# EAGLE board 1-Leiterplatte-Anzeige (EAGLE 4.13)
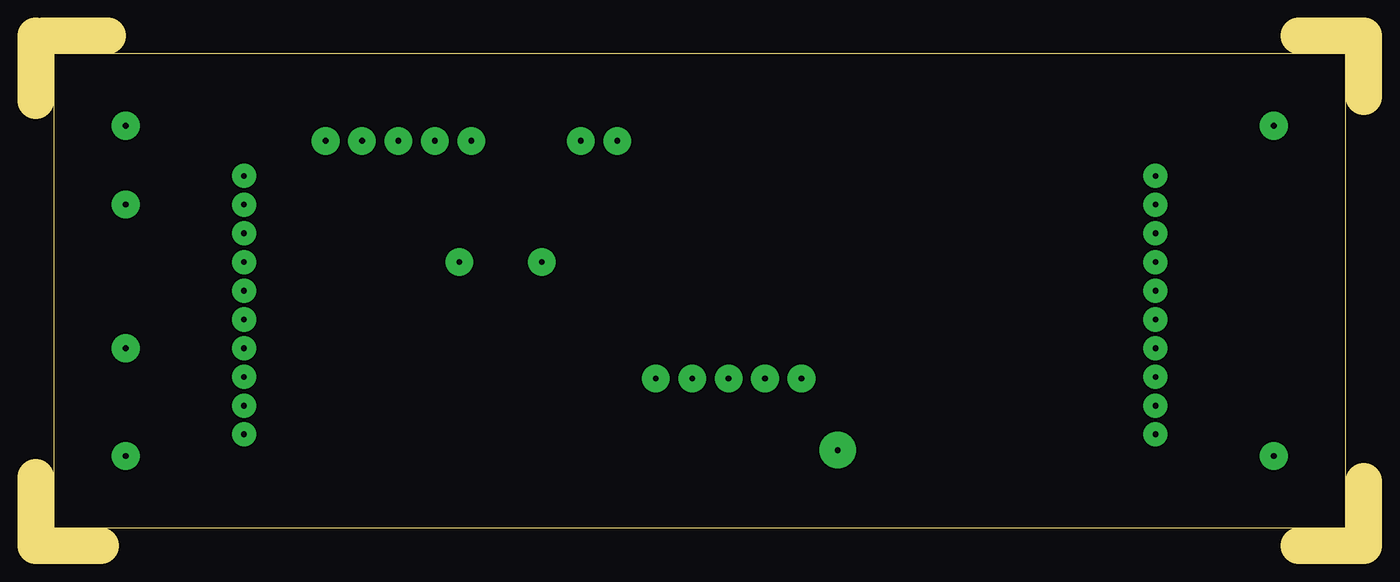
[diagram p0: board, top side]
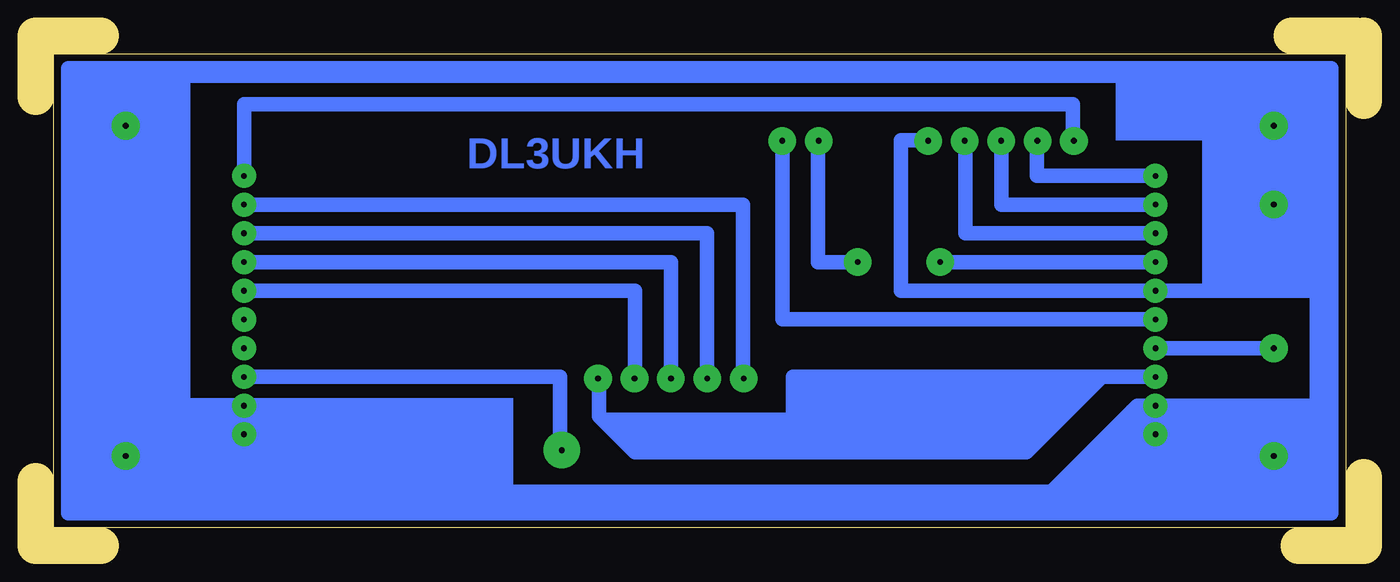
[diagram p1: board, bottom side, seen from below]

Size 92.5 x 35.5 mm. Coordinates in mm from the lower left corner, seen from the top.
Outline: 0.5,35.5 5,35.5
Outline: 0,31 0,35.5
Outline: 0,0.25 0,4.75
Outline: 4.5,0 0,0
Outline: 88,35.5 92.5,35.5 92.5,31.25
Outline: 92.5,4.5 92.5,0 88,0
Outline: 1.25,1.25 91.25,1.25 91.25,34.25 1.25,34.25 1.25,1.25
Copper layers (1*16): Top 0.035mm / dielectric 1.5mm / Bottom 0.035mm
Design rules "default": minimum track width 10mil, minimum drill 24mil, track to track 8mil, track to pad 8mil, pad to pad 8mil, via to via 8mil, smd to smd 8mil, copper to edge 40mil, drill to drill 8mil, minimum pad ring 10mil, minimum via ring 8mil, stop-mask expansion 4mil, vias tented up to drill 0mil, thermal gap 10mil

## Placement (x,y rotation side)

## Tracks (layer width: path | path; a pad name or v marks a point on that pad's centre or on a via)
S$1  (via drill 0.4 pad 1.93)
  other vias: 6.25,6.25
S$2  (via drill 0.4 pad 1.93)
  other vias: 6.25,29.25
S$3  (via drill 0.4 pad 1.93)
  other vias: 86.25,6.25
S$4  (via drill 0.4 pad 1.93)
  other vias: 86.25,29.25
S$5
  Bottom 1.016: 82.25,2.5 82.25,33.25 87,33.25 | 10,33.25 10.25,33.25 | 10,33.25 87,33.25 | 87,33.25 90.25,33.25 90.25,2.25 2.25,2.25 2.25,33.25 10,33.25
S$6  (via drill 0.4 pad 1.68, 0.4 pad 1.93)
  Bottom 1.016: 43.25,11.75 43.25,23.75 v78,23.75
  other vias: 43.18,11.65
S$7  (via drill 0.4 pad 1.68, 0.4 pad 1.93)
  Bottom 1.016: 6,13.75 v14.5,13.75 | 2.5,17.75 3.25,17.75 | 3.25,17.75 v14.5,17.75 32.25,17.75 32.25,28.25 30.25,28.25 | 20.75,3.75 16.75,7.75 v14.5,7.75 | 22,3.5 15.75,9.75 v14.5,9.75 | v14.5,7.75 9.5,7.75 | v14.5,9.75 v14.5,7.75 | 10.25,9.75 v14.5,9.75 | 10.25,9.75 3.25,9.75 | 3.25,9.75 2.75,9.75 | 10.25,2.5 10.25,9.75 | 3.25,17.75 3.25,9.75
  other vias: 30.34,28.19
S$8  (via drill 0.4 pad 1.68)
  Bottom 1.016: v14.5,15.75 22.75,15.75
S$10  (via drill 0.4 pad 1.68, 0.4 pad 1.93)
  Bottom 1.016: v14.5,19.75 v29.5,19.75
S$11  (via drill 0.4 pad 1.93)
  other vias: 6.25,13.75
S$12  (via drill 0.4 pad 1.93)
  other vias: 6.25,23.75
S$14  (via drill 0.4 pad 1.68)
  Bottom 1.016: v78,9.75 82.5,9.75
S$15  (via drill 0.4 pad 1.68, 0.4 pad 1.93)
  Bottom 1.016: 45.75,11.75 45.75,21.75 v78,21.75
  other vias: 45.72,11.65
S$16  (via drill 0.4 pad 1.68)
  other vias: 78,13.75
S$17  (via drill 0.4 pad 1.68)
  other vias: 78,15.75
S$18  (via drill 0.4 pad 1.68, 0.4 pad 1.93)
  Bottom 1.016: 48.25,11.75 48.25,19.75 v78,19.75
  other vias: 48.26,11.65
S$19  (via drill 0.4 pad 1.68, 0.4 pad 1.93)
  Bottom 1.016: 50.75,11.75 50.75,17.75 v78,17.75
  other vias: 50.8,11.65
S$20  (via drill 0.4 pad 1.68, 0.4 pad 1.93)
  Bottom 1.016: 20.25,28 20.25,30.75 24.75,30.75 | 24.75,30.75 25,30.75 | 24.75,30.75 78,30.75 v78,25.75
  other vias: 20.18,28.19
S$22  (via drill 0.4 pad 1.93)
  Bottom 1.016: v35.25,19.75 38,19.75 38,28.25
  other vias: 37.96,28.19
S$26  (via drill 0.4 pad 1.68, 0.4 pad 1.93)
  Bottom 1.016: v14.5,15.75 40.5,15.75 40.5,28.25
  other vias: 40.5,28.19
S$27  (via drill 0.4 pad 1.68, 0.4 pad 1.93)
  Bottom 1.016: v14.5,23.75 25.25,23.75 25.25,28.25
  other vias: 25.26,28.19
S$30  (via drill 0.4 pad 1.68, 0.4 pad 1.93)
  Bottom 1.016: 27.75,28.25 27.75,21.75 v14.5,21.75
  other vias: 27.8,28.19
S$33  (via drill 0.4 pad 1.68, 0.4 pad 1.93)
  Bottom 1.016: 53.25,11.75 53.25,9 50.75,6.5 39.75,6.5 | 39.75,6.5 23.5,6.5 18.25,11.75 17.75,11.75 | 17.75,11.75 v14.5,11.75 | 17.75,11.75 39.75,11.75 39.75,6.5
  other vias: 53.34,11.65
S$35  (via drill 0.4 pad 1.68, 0.4 pad 2.54)
  Bottom 1.016: 56,6.75 56,11.75 v78,11.75
  other vias: 55.86,6.65
S$37  (via drill 0.4 pad 1.68)
  Bottom 1.016: v78,7.75 82.5,7.75
S$38  (via drill 0.4 pad 1.68, 0.4 pad 1.93)
  Bottom 1.016: v14.5,25.75 22.75,25.75 22.75,28.25
  other vias: 22.72,28.19
(copper drawn outside any net)
  shapes: Bottom area x22

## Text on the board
Bottom: DL3UKH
